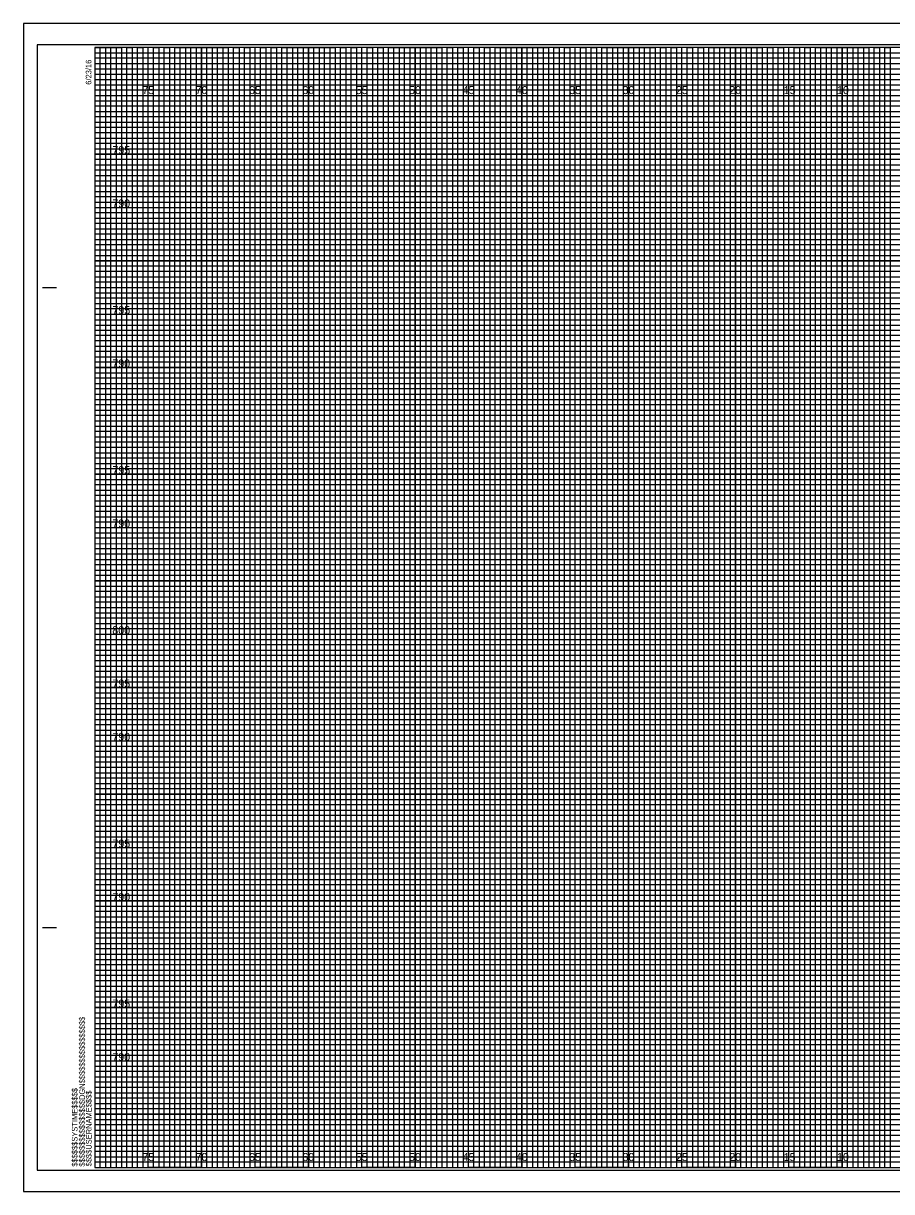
# Model space of a CAD drawing. Extents: x -7 to 162, y -2 to 107.
# Drawn here: x -6.7 to 74.6, y -2.3 to 107.3 of the extents above; entities that cross this region are included whole.
import ezdxf

# ---------------------------------------------------------------- set-up
doc = ezdxf.new("R2010")
doc.units = 0
for name, color, linetype in [('Exist Cross Section Cell', 7, 'Continuous'), ('Exist XS Center Line Elevation Label', 7, 'Continuous'), ('Prop CMT Conc Surface', 7, 'Continuous'), ('Prop CMT Concrete Structures', 7, 'Continuous'), ('Prop CMT Pvmt Course 1', 7, 'Continuous'), ('Prop CMT Pvmt Course 1 CG', 7, 'Continuous'), ('Prop CMT Pvmt Course 1 Wedge', 7, 'Continuous'), ('Prop CMT Pvmt Course 2', 7, 'Continuous'), ('Prop CMT Pvmt Course 3', 7, 'Continuous'), ('Prop CMT Slope Grass', 7, 'Continuous'), ('Prop CMT Subgrade Earthwork', 7, 'Continuous')]:
    doc.layers.add(name, color=color, linetype=linetype)

msp = doc.modelspace()

# ---------------------------------------------------------------- linework, layer by layer
at = {"layer": 'Exist Cross Section Cell'}
for p, q in [((5, 105), (0, 105)), ((5, 0), (5, 105)), ((15, 105), (10, 105)), ((10, 105), (10, 0)), ((15, 0), (15, 105)), ((25, 105), (20, 105)), ((20, 105), (20, 0)), ((25, 0), (25, 105)), ((35, 105), (30, 105)), ((30, 105), (30, 0)), ((35, 0), (35, 105)), ((45, 105), (40, 105)), ((40, 105), (40, 0)), ((45, 0), (45, 105)), ((55, 105), (50, 105)), ((50, 105), (50, 0)), ((55, 0), (55, 105)), ((65, 105), (60, 105)), ((60, 105), (60, 0)), ((65, 0), (65, 105)), ((75, 105), (70, 105)), ((70, 105), (70, 0)), ((10, 0), (5, 0)), ((20, 0), (15, 0)), ((30, 0), (25, 0)), ((40, 0), (35, 0)), ((50, 0), (45, 0)), ((60, 0), (55, 0)), ((70, 0), (65, 0))]:
    msp.add_line(p, q, dxfattribs=at)
for points in [[(0, 100), (160, 100), (160, 95), (0, 95)], [(0, 90), (160, 90), (160, 85), (0, 85)], [(0, 80), (160, 80), (160, 75), (0, 75)], [(0, 70), (160, 70), (160, 65), (0, 65)], [(0, 60), (160, 60), (160, 55), (0, 55)], [(0, 50), (160, 50), (160, 45), (0, 45)], [(0, 40), (160, 40), (160, 35), (0, 35)], [(0, 30), (160, 30), (160, 25), (0, 25)], [(0, 20), (160, 20), (160, 15), (0, 15)], [(0, 10), (160, 10), (160, 5), (0, 5)]]:
    msp.add_lwpolyline(points, dxfattribs=at)
at = {"layer": 'Exist XS Center Line Elevation Label'}
for points in [[(0, 105), (2.5, 105), (2.5, 0), (7.5, 0), (7.5, 105), (12.5, 105), (12.5, 0), (17.5, 0), (17.5, 105), (22.5, 105), (22.5, 0), (27.5, 0), (27.5, 105), (32.5, 105), (32.5, 0), (37.5, 0), (37.5, 105), (42.5, 105), (42.5, 0), (47.5, 0), (47.5, 105), (52.5, 105), (52.5, 0), (57.5, 0), (57.5, 105), (62.5, 105), (62.5, 0), (67.5, 0), (67.5, 105), (72.5, 105), (72.5, 0), (77.5, 0)], [(0, 102.5), (137.5, 102.5)], [(0, 92.5), (160, 92.5), (160, 97.5), (0, 97.5)], [(0, 82.5), (160, 82.5), (160, 87.5), (0, 87.5)], [(0, 72.5), (160, 72.5), (160, 77.5), (0, 77.5)], [(0, 62.5), (160, 62.5), (160, 67.5), (0, 67.5)], [(0, 52.5), (160, 52.5), (160, 57.5), (0, 57.5)], [(0, 42.5), (160, 42.5), (160, 47.5), (0, 47.5)], [(0, 32.5), (160, 32.5), (160, 37.5), (0, 37.5)], [(0, 22.5), (160, 22.5), (160, 27.5), (0, 27.5)], [(0, 12.5), (160, 12.5), (160, 17.5), (0, 17.5)], [(0, 2.5), (160, 2.5), (160, 7.5), (0, 7.5)]]:
    msp.add_lwpolyline(points, dxfattribs=at)
at = {"layer": 'Prop CMT Conc Surface'}
for p, q in [((5, 0), (5, 105)), ((10, 0), (10, 105)), ((15, 0), (15, 105)), ((20, 0), (20, 105)), ((25, 0), (25, 105)), ((30, 0), (30, 105)), ((35, 0), (35, 105)), ((40, 0), (40, 105)), ((45, 0), (45, 105)), ((50, 0), (50, 105)), ((55, 0), (55, 105)), ((60, 0), (60, 105)), ((65, 0), (65, 105)), ((70, 0), (70, 105)), ((0, 100), (160, 100)), ((0, 95), (160, 95)), ((0, 90), (160, 90)), ((0, 85), (160, 85)), ((0, 80), (160, 80)), ((0, 75), (160, 75)), ((0, 70), (160, 70)), ((0, 65), (160, 65)), ((0, 60), (160, 60)), ((0, 55), (160, 55)), ((0, 50), (160, 50)), ((0, 45), (160, 45)), ((0, 40), (160, 40)), ((0, 35), (160, 35)), ((0, 30), (160, 30)), ((0, 25), (160, 25)), ((0, 20), (160, 20)), ((0, 15), (160, 15)), ((0, 10), (160, 10)), ((0, 5), (160, 5))]:
    msp.add_line(p, q, dxfattribs=at)
at = {"layer": 'Prop CMT Concrete Structures'}
for points in [[(0, 0), (0.5, 0), (0.5, 105), (1, 105), (1, 0)], [(1, 0), (1.5, 0), (1.5, 105), (2, 105), (2, 0)], [(2.5, 0), (3, 0), (3, 105), (3.5, 105), (3.5, 0)], [(3.5, 0), (4, 0), (4, 105), (4.5, 105), (4.5, 0)], [(5, 0), (5.5, 0), (5.5, 105), (6, 105), (6, 0)], [(6, 0), (6.5, 0), (6.5, 105), (7, 105), (7, 0)], [(7.5, 0), (8, 0), (8, 105), (8.5, 105), (8.5, 0)], [(8.5, 0), (9, 0), (9, 105), (9.5, 105), (9.5, 0)], [(10, 0), (10.5, 0), (10.5, 105), (11, 105), (11, 0)], [(11, 0), (11.5, 0), (11.5, 105), (12, 105), (12, 0)], [(12.5, 0), (13, 0), (13, 105), (13.5, 105), (13.5, 0)], [(13.5, 0), (14, 0), (14, 105), (14.5, 105), (14.5, 0)], [(15, 0), (15.5, 0), (15.5, 105), (16, 105), (16, 0)], [(16, 0), (16.5, 0), (16.5, 105), (17, 105), (17, 0)], [(17.5, 0), (18, 0), (18, 105), (18.5, 105), (18.5, 0)], [(18.5, 0), (19, 0), (19, 105), (19.5, 105), (19.5, 0)], [(20, 0), (20.5, 0), (20.5, 105), (21, 105), (21, 0)], [(21, 0), (21.5, 0), (21.5, 105), (22, 105), (22, 0)], [(22.5, 0), (23, 0), (23, 105), (23.5, 105), (23.5, 0)], [(23.5, 0), (24, 0), (24, 105), (24.5, 105), (24.5, 0)], [(25, 0), (25.5, 0), (25.5, 105), (26, 105), (26, 0)], [(26, 0), (26.5, 0), (26.5, 105), (27, 105), (27, 0)], [(27.5, 0), (28, 0), (28, 105), (28.5, 105), (28.5, 0)], [(28.5, 0), (29, 0), (29, 105), (29.5, 105), (29.5, 0)], [(30, 0), (30.5, 0), (30.5, 105), (31, 105), (31, 0)], [(31, 0), (31.5, 0), (31.5, 105), (32, 105), (32, 0)], [(32.5, 0), (33, 0), (33, 105), (33.5, 105), (33.5, 0)], [(33.5, 0), (34, 0), (34, 105), (34.5, 105), (34.5, 0)], [(35, 0), (35.5, 0), (35.5, 105), (36, 105), (36, 0)], [(36, 0), (36.5, 0), (36.5, 105), (37, 105), (37, 0)], [(37.5, 0), (38, 0), (38, 105), (38.5, 105), (38.5, 0)], [(38.5, 0), (39, 0), (39, 105), (39.5, 105), (39.5, 0)], [(40, 0), (40.5, 0), (40.5, 105), (41, 105), (41, 0)], [(41, 0), (41.5, 0), (41.5, 105), (42, 105), (42, 0)], [(42.5, 0), (43, 0), (43, 105), (43.5, 105), (43.5, 0)], [(43.5, 0), (44, 0), (44, 105), (44.5, 105), (44.5, 0)], [(45, 0), (45.5, 0), (45.5, 105), (46, 105), (46, 0)], [(46, 0), (46.5, 0), (46.5, 105), (47, 105), (47, 0)], [(47.5, 0), (48, 0), (48, 105), (48.5, 105), (48.5, 0)], [(48.5, 0), (49, 0), (49, 105), (49.5, 105), (49.5, 0)], [(50, 0), (50.5, 0), (50.5, 105), (51, 105), (51, 0)], [(51, 0), (51.5, 0), (51.5, 105), (52, 105), (52, 0)], [(52.5, 0), (53, 0), (53, 105), (53.5, 105), (53.5, 0)], [(53.5, 0), (54, 0), (54, 105), (54.5, 105), (54.5, 0)], [(55, 0), (55.5, 0), (55.5, 105), (56, 105), (56, 0)], [(56, 0), (56.5, 0), (56.5, 105), (57, 105), (57, 0)], [(57.5, 0), (58, 0), (58, 105), (58.5, 105), (58.5, 0)], [(58.5, 0), (59, 0), (59, 105), (59.5, 105), (59.5, 0)], [(60, 0), (60.5, 0), (60.5, 105), (61, 105), (61, 0)], [(61, 0), (61.5, 0), (61.5, 105), (62, 105), (62, 0)], [(62.5, 0), (63, 0), (63, 105), (63.5, 105), (63.5, 0)], [(63.5, 0), (64, 0), (64, 105), (64.5, 105), (64.5, 0)], [(65, 0), (65.5, 0), (65.5, 105), (66, 105), (66, 0)], [(66, 0), (66.5, 0), (66.5, 105), (67, 105), (67, 0)], [(67.5, 0), (68, 0), (68, 105), (68.5, 105), (68.5, 0)], [(68.5, 0), (69, 0), (69, 105), (69.5, 105), (69.5, 0)], [(70, 0), (70.5, 0), (70.5, 105), (71, 105), (71, 0)], [(71, 0), (71.5, 0), (71.5, 105), (72, 105), (72, 0)], [(72.5, 0), (73, 0), (73, 105), (73.5, 105), (73.5, 0)], [(73.5, 0), (74, 0), (74, 105), (74.5, 105), (74.5, 0)]]:
    msp.add_lwpolyline(points, dxfattribs=at)
at = {"layer": 'Prop CMT Pvmt Course 1'}
msp.add_lwpolyline([(-5.4, -0.25), (161.2, -0.25), (161.2, 105.25), (-5.4, 105.25)], close=True, dxfattribs=at)
at = {"layer": 'Prop CMT Pvmt Course 1 CG'}
msp.add_lwpolyline([(-6.7, -2.25), (161.65, -2.25), (161.65, 107.25), (-6.7, 107.25)], close=True, dxfattribs=at)
at = {"layer": 'Prop CMT Pvmt Course 2'}
for p, q in [((0, 104.5), (130, 104.5)), ((130, 103.99), (0, 103.99)), ((0, 103.99), (0, 103.5)), ((0, 103.5), (130, 103.5)), ((130, 102.95), (0, 102.95)), ((0, 102.95), (0, 102)), ((0, 102), (160, 102))]:
    msp.add_line(p, q, dxfattribs=at)
for points in [[(0, 101.5), (135, 101.5), (160, 101.5), (160, 101), (0, 101)], [(0, 100.5), (160, 100.5), (160, 99.5), (0, 99.5)], [(0, 99), (160, 99), (160, 98.5), (0, 98.49)], [(0, 98), (160, 98), (160, 97), (0, 97)], [(0, 96.5), (160, 96.5), (160, 96), (0, 96)], [(0, 95.5), (160, 95.5), (160, 94.5), (0, 94.5)], [(0, 94), (160, 94), (160, 93.5), (0, 93.5)], [(0, 93), (160, 93), (160, 92), (0, 92)], [(0, 91.5), (160, 91.5), (160, 91), (0, 91)], [(0, 90.5), (160, 90.5), (160, 89.5), (0, 89.5)], [(0, 89), (160, 89), (160, 88.5), (0, 88.5)], [(0, 88), (160, 88), (160, 86.98), (160, 86.5), (160, 86), (0, 86)], [(0, 87), (160, 87), (160, 86.5), (0, 86.5)], [(0, 85.5), (160, 85.5), (160, 84.5), (0, 84.52)], [(0, 84.52), (160, 84.5), (160, 84), (0, 84)], [(0, 83.5), (160, 83.5), (160, 83), (0, 83)], [(0, 82), (160, 82), (160, 81.5), (0, 81.5)], [(0, 81), (160, 81), (160, 80.5), (0, 80.5)], [(-0.04, 79.45), (160, 79.45), (160, 78.94), (-0.04, 78.94)], [(0, 78.5), (160, 78.5), (160, 78), (0, 78)], [(0, 77), (160, 77), (160, 76.5), (0, 76.5)], [(0, 76), (160, 76), (160, 75.5), (0, 75.5)], [(0, 74.5), (160, 74.5), (160, 74), (0, 74)], [(0, 73.5), (160, 73.5), (160, 73), (0, 73)], [(0, 72), (160, 72), (160, 71.5), (0, 71.5)], [(0, 71), (160, 71), (160, 70.5), (0, 70.5)], [(0, 69.5), (160, 69.5), (160, 68.99), (0, 69)], [(0, 68.5), (160, 68.5), (160, 68), (0, 68)], [(0, 67), (160, 67), (160, 66.5), (0, 66.5)], [(0, 66), (160, 66), (160, 65.5), (0, 65.5)], [(0, 64.5), (160, 64.5), (160, 64), (0, 64)], [(0, 63.5), (160, 63.5), (160, 63), (0, 63)], [(0, 62), (160, 62), (160, 61.5), (0, 61.5)], [(0, 61), (160, 61), (160, 60.5), (0, 60.5)], [(0, 59.5), (160, 59.5), (160, 59), (0, 59)], [(0, 58.5), (160.03, 58.45), (160, 58), (0, 58)], [(0, 57), (160, 57), (160, 56.5), (0, 56.5)], [(0, 56), (160, 56), (160, 55.5), (0, 55.5)], [(0, 54.5), (160, 54.5), (160, 54), (0, 54)], [(0, 53.5), (160, 53.5), (160, 53), (0, 53)], [(0, 52), (160, 52), (160, 51.5), (0, 51.5)], [(0, 51), (160, 51), (160, 50.5), (0, 50.5)], [(0, 49.5), (160, 49.5), (160, 49), (0, 49)], [(0, 48.5), (160, 48.5), (160, 48), (0, 48)], [(0, 47), (160, 47), (160, 46.5), (0, 46.5)], [(0, 46), (160, 46), (160, 45.5), (0, 45.5)], [(0, 44.5), (160, 44.5), (160, 44), (0, 44)], [(0, 43.5), (160, 43.5), (160, 43), (0, 43)], [(0, 42), (160, 42), (160, 41.5), (0, 41.5)], [(0, 41), (160, 41), (160, 40.5), (0, 40.5)], [(0, 39.5), (160, 39.5), (160, 38.99), (0, 39)], [(0, 38.5), (160, 38.5), (160, 38), (0, 38)], [(0, 37), (160, 37), (160, 36.5), (0, 36.5)], [(0, 36), (160, 36), (160, 35.5), (0, 35.5)], [(0, 34.5), (160, 34.5), (160, 34), (0, 34)], [(0, 33.5), (160, 33.5), (160, 33), (0, 33)], [(0, 32), (160, 32), (160, 31.5), (0, 31.5)], [(0, 31), (160, 31), (160, 30.5), (0, 30.5)], [(0, 29.5), (160, 29.5), (160, 29), (0, 29)], [(0, 28.5), (160.03, 28.46), (160, 28), (0, 28)], [(0, 27), (160, 27), (160, 26.5), (0, 26.5)], [(0, 26), (160, 26), (160, 25.5), (0, 25.5)], [(0, 24.5), (160, 24.5), (160, 24), (0, 24)], [(0, 23.5), (160, 23.5), (160, 23), (0, 23)], [(0, 22), (160, 22), (160, 21.5), (0, 21.5)], [(0, 21), (160, 21), (160, 20.5), (0, 20.5)], [(0, 19.5), (160, 19.5), (160, 19), (0, 19)], [(0, 18.5), (160, 18.5), (160, 18), (0, 18)], [(0, 17), (160, 17), (160, 16.5), (0, 16.5)], [(0, 16), (160, 16), (160, 15.5), (0, 15.5)], [(0, 14.5), (160, 14.5), (160, 14), (0, 14)], [(0, 13.5), (160, 13.5), (160, 13), (0, 13)], [(0, 12), (160, 12), (160, 11.5), (0, 11.5)], [(0, 11), (160, 11), (160, 10.5), (0, 10.5)], [(0, 9.5), (160, 9.5), (160, 9), (0, 9)], [(0, 8.5), (160, 8.5), (160, 8), (0, 8)], [(0, 7), (160, 7), (160, 6.5), (0, 6.5)], [(0, 6), (160, 6), (160, 5.5), (0, 5.5)], [(0, 4.5), (160, 4.5), (160, 4), (0, 4)], [(0, 3.5), (160, 3.5), (160, 3), (0, 3)], [(0, 2), (160, 2), (160, 1.5), (0, 1.5)], [(0, 1), (160, 1), (160, 0.5), (0, 0.5)]]:
    msp.add_lwpolyline(points, dxfattribs=at)
at = {"layer": 'Prop CMT Pvmt Course 3'}
for p, q in [((-4.9, 82.5), (-3.65, 82.5)), ((-4.85, 82.5), (-3.6, 82.5)), ((-4.9, 22.5), (-3.65, 22.5)), ((-4.85, 22.5), (-3.6, 22.5)), ((0, 0), (0, 0)), ((0, 0), (0, 0)), ((0, 0), (0, 0)), ((0, 0), (0, 0)), ((0, 0), (0, 0)), ((0, 0), (0, 0)), ((0, 0), (0, 0))]:
    msp.add_line(p, q, dxfattribs=at)
msp.add_lwpolyline([(160, 105), (0, 105), (0, 0), (160, 0)], close=True, dxfattribs=at)
at = {"layer": 'Prop CMT Subgrade Earthwork'}
for p, q in [((161.65, 107.25), (-6.7, 107.25)), ((-6.7, 107.25), (-6.7, -2.25)), ((-6.7, -2.25), (161.65, -2.25))]:
    msp.add_line(p, q, dxfattribs=at)

# ---------------------------------------------------------------- texts
at = {"layer": 'Prop CMT Pvmt Course 1 Wedge'}
for s, p in [('75', (4.44, 100.62)), ('70', (9.43, 100.62)), ('65', (14.44, 100.62)), ('60', (19.43, 100.62)), ('55', (24.44, 100.62)), ('50', (29.43, 100.62)), ('45', (34.44, 100.62)), ('40', (39.43, 100.62)), ('35', (44.44, 100.62)), ('30', (49.43, 100.62)), ('25', (54.44, 100.62)), ('20', (59.43, 100.62)), ('15', (64.53, 100.62)), ('10', (69.52, 100.62)), ('75', (4.44, 0.62)), ('70', (9.43, 0.62)), ('65', (14.44, 0.62)), ('60', (19.43, 0.62)), ('55', (24.44, 0.62)), ('50', (29.43, 0.62)), ('45', (34.44, 0.62)), ('40', (39.43, 0.62)), ('35', (44.44, 0.62)), ('30', (49.43, 0.62)), ('25', (54.44, 0.62)), ('20', (59.43, 0.62)), ('15', (64.53, 0.62)), ('10', (69.52, 0.62))]:
    msp.add_text(s, height=0.75, dxfattribs=at).set_placement(p)
at = {"layer": 'Prop CMT Pvmt Course 3'}
for s, p in [('6/23/16', (-0.33, 101.5)), ('$$$$$$$$$$$$$$$$DGN$$$$$$$$$$$$$$$$', (-0.94, 0.09)), ('$$$$$$SYSTIME$$$$$', (-1.63, 0.09)), ('$$$$USERNAME$$$$', (-0.31, 0.12))]:
    msp.add_text(s, height=0.525, rotation=90, dxfattribs=at).set_placement(p)
at = {"layer": 'Prop CMT Slope Grass'}
for s, p in [('795', (1.64, 95)), ('790', (1.63, 90)), ('795', (1.64, 80)), ('790', (1.63, 75)), ('795', (1.64, 65)), ('790', (1.63, 60)), ('800', (1.63, 50)), ('795', (1.64, 45)), ('790', (1.63, 40)), ('795', (1.64, 30)), ('790', (1.63, 25)), ('795', (1.64, 15)), ('790', (1.63, 10))]:
    msp.add_text(s, height=0.75, dxfattribs=at).set_placement(p)

doc.saveas('drawing.dxf')
